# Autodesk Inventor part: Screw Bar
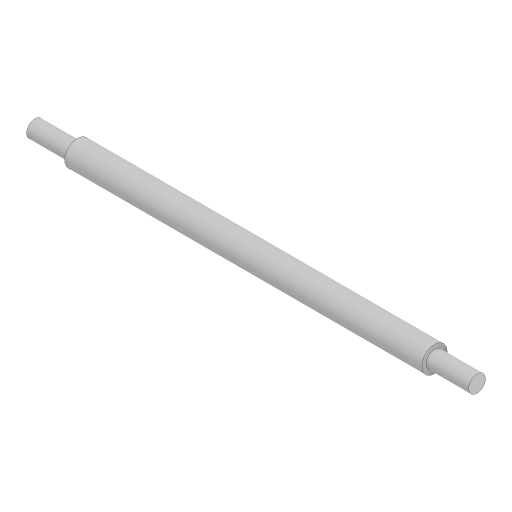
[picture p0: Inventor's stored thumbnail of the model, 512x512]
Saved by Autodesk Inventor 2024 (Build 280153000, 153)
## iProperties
Created: 2016-03
Part Number: Screw Bar
Material: Generic
Document SubType Name: Modeling
Designer: Sandeep
Density: 1 g/cm^3
Appearance: Default
Mass: 2.62637 g
Surface Area: 18.9124 cm^2
Volume: 2.62637 cm^3
Author: Sandeep
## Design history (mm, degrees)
sketch "Sketch1"
  geometry: L1 (-104, 2)-(-94, 2); L2 (-94, 2)-(-94, 3); L3 (-94, 3)-(-10, 3); L4 (-10, 3)-(-10, 2); L5 (-10, 2)-(0, 2); L6 (0, 2)-(0, 0); L7 (-104, 2)-(-104, 0); L8 (-104, 0)-(0, 0); L9 (0, 0)-(21.698, 0)
  constraints: 18 end point, 4 perpendicular, 3 horizontal, 2 point on line, 1 vertical
  dimensions: "d0" = 4 diameter of L5 L9; "d1" = 6 diameter of L3 L9; "d2" = 10 distance of L4.end L5.end; "d3" = 10 distance of L1.start L1.end; "d4" = 104 distance between parallel lines of L7 L6
revolve "Revolution1" sketch "Sketch1" stored, may be unused: angle "d5" = 90 deg
body "Solid1"
